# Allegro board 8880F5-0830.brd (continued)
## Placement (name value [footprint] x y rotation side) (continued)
NOREF#2145  -  []  298.49 288.91 90 top
NOREF#2146  -  []  201.49 165.4 90 top
NOREF#2147  -  []  351.04 241.69 0 top
NOREF#2148  -  []  451.68 230.2 0 top
NOREF#2149  -  []  229.51 189.2 0 top
NOREF#2150  -  []  393.74 131.34 90 top
NOREF#2151  -  []  332.51 264.35 90 top
NOREF#2152  -  []  167.7 229.07 90 top
NOREF#2153  -  []  392.24 193.43 0 top
NOREF#2154  -  []  107.18 246.83 90 top
NOREF#2155  -  []  377.32 180.15 0 top
NOREF#2156  -  []  306.71 131.64 0 top
NOREF#2157  -  []  333.4 265.56 0 top
NOREF#2158  -  []  301.56 190.49 0 top
NOREF#2159  -  []  465.31 230.2 0 top
NOREF#2160  -  []  336.77 165.04 90 top
NOREF#2161  -  []  167.7 178.86 90 top
NOREF#2162  -  []  217.83 174.63 90 top
NOREF#2163  -  []  308.14 296.86 0 top
NOREF#2164  -  []  249.6 224.74 90 top
NOREF#2165  -  []  478.57 291.28 90 top
NOREF#2166  -  []  192.47 222.95 90 top
NOREF#2167  -  []  122.44 171.1 0 top
NOREF#2168  -  []  352.55 242.64 0 top
NOREF#2169  -  []  250.17 165.04 90 top
NOREF#2170  -  []  215.96 248.49 0 top
NOREF#2171  -  []  237.83 257.63 0 top
NOREF#2172  -  []  201.23 219.75 90 top
NOREF#2173  -  []  395.2 233.11 0 top
NOREF#2174  -  []  192.47 182.06 90 top
NOREF#2175  -  []  272.25 242.32 90 top
NOREF#2176  -  []  167.7 178.86 90 top
NOREF#2177  -  []  310.43 187.61 90 top
NOREF#2178  -  []  201.49 151.93 90 top
NOREF#2179  -  []  343.98 288.86 0 top
NOREF#2180  -  []  310.43 186.34 0 top
NOREF#2181  -  []  94.68 234.24 0 top
NOREF#2182  -  []  330.73 264.35 90 top
NOREF#2183  -  []  209.23 216.45 90 top
NOREF#2184  -  []  182.57 212.85 0 top
NOREF#2185  -  []  127.81 175.44 90 top
NOREF#2186  -  []  175.8 215.25 90 top
NOREF#2187  -  []  254.29 265.56 90 top
NOREF#2188  -  []  272.25 181.69 0 top
NOREF#2189  -  []  175.7 218.65 90 top
NOREF#2190  -  []  402.14 146.88 0 top
NOREF#2191  -  []  399.39 161.74 0 top
NOREF#2192  -  []  223.56 233.86 90 top
NOREF#2193  -  []  339.65 265.86 90 top
NOREF#2194  -  []  248.96 164.74 0 top
NOREF#2195  -  []  384.36 131.89 0 top
NOREF#2196  -  []  409.49 180.15 0 top
NOREF#2197  -  []  391.8 209.36 0 top
NOREF#2198  -  []  297.83 234.63 90 top
NOREF#2199  -  []  168.13 213.45 90 top
NOREF#2200  -  []  327.57 264.65 90 top
NOREF#2201  -  []  327.25 205.55 0 top
NOREF#2202  -  []  184.47 214 90 top
NOREF#2203  -  []  351.34 245.18 0 top
NOREF#2204  -  []  392.73 154.88 0 top
NOREF#2205  -  []  459.28 227 90 top
NOREF#2206  -  []  449.99 217.9 0 top
NOREF#2207  -  []  320.42 139.64 0 top
NOREF#2208  -  []  322.23 173.13 90 top
NOREF#2209  -  []  122.41 178.64 0 top
NOREF#2210  -  []  167.7 242.78 90 top
NOREF#2211  -  []  371.73 281.11 0 top
NOREF#2212  -  []  265.39 135.19 0 top
NOREF#2213  -  []  234.33 168.13 90 top
NOREF#2214  -  []  184.47 187.92 90 top
NOREF#2215  -  []  270.04 280.1 0 top
NOREF#2216  -  []  223.15 211.32 90 top
NOREF#2217  -  []  201.23 206.29 90 top
NOREF#2218  -  []  313.98 131.19 90 top
NOREF#2219  -  []  413.71 178.82 0 top
NOREF#2220  -  []  397.57 131.89 0 top
NOREF#2221  -  []  262.36 165.04 90 top
NOREF#2222  -  []  182.82 189.04 90 top
NOREF#2223  -  []  184.89 186.02 90 top
NOREF#2224  -  []  222.11 252.14 0 top
NOREF#2225  -  []  251.62 205.56 0 top
NOREF#2226  -  []  309.05 271.67 0 top
NOREF#2227  -  []  175.7 243.88 90 top
NOREF#2228  -  []  390.94 257.16 90 top
NOREF#2229  -  []  259.59 133.29 90 top
NOREF#2230  -  []  467.51 230.2 0 top
NOREF#2231  -  []  192.47 191.22 90 top
NOREF#2232  -  []  397.8 146.43 90 top
NOREF#2233  -  []  155.57 289.11 90 top
NOREF#2234  -  []  251.94 265.86 90 top
NOREF#2235  -  []  422.7 163.64 0 top
NOREF#2236  -  []  272.24 249.18 90 top
NOREF#2237  -  []  248.33 187.93 0 top
NOREF#2238  -  []  101.82 290.38 90 top
NOREF#2239  -  []  328.96 224.72 0 top
NOREF#2240  -  []  300.36 248.49 0 top
NOREF#2241  -  []  342.68 163.52 90 top
NOREF#2242  -  []  472.86 210.36 90 top
NOREF#2243  -  []  230.41 246.34 90 top
NOREF#2244  -  []  313.98 131.09 90 top
NOREF#2245  -  []  194.09 146.68 90 top
NOREF#2246  -  []  295.96 237.06 0 top
NOREF#2247  -  []  325.92 131.64 0 top
NOREF#2248  -  []  462.06 293.82 90 top
NOREF#2249  -  []  330.51 288.86 0 top
NOREF#2250  -  []  124.1 231.22 0 top
NOREF#2251  -  []  394.66 242.38 90 top
NOREF#2252  -  []  424.98 146.33 90 top
NOREF#2253  -  []  263.95 224.74 90 top
NOREF#2254  -  []  167.7 200.54 0 top
NOREF#2255  -  []  115.99 130.36 90 top
NOREF#2256  -  []  343.95 164.74 90 top
NOREF#2257  -  []  388.66 139.89 0 top
NOREF#2258  -  []  112.67 171.02 0 top
NOREF#2259  -  []  250.49 224.74 90 top
NOREF#2260  -  []  201.23 201.89 90 top
NOREF#2261  -  []  250.49 223.52 90 top
NOREF#2262  -  []  482.64 192.46 90 top
NOREF#2263  -  []  369.38 224.6 0 top
NOREF#2264  -  []  117.01 234.24 90 top
NOREF#2265  -  []  354.27 138.37 90 top
NOREF#2266  -  []  485.36 292.02 90 top
NOREF#2267  -  []  389.7 209.36 0 top
NOREF#2268  -  []  330.17 163.82 90 top
NOREF#2269  -  []  342.04 224.72 0 top
NOREF#2270  -  []  471.21 211.76 90 top
NOREF#2271  -  []  175.7 189.02 90 top
NOREF#2272  -  []  346.27 135.17 90 top
NOREF#2273  -  []  209.33 228.97 90 top
NOREF#2274  -  []  375.22 163.39 0 top
NOREF#2275  -  []  120.21 178.64 0 top
NOREF#2276  -  []  210.86 201.29 90 top
NOREF#2277  -  []  383.09 289.12 0 top
NOREF#2278  -  []  385.19 249.11 0 top
NOREF#2279  -  []  310.73 183.41 0 top
NOREF#2280  -  []  378.75 240.56 90 top
NOREF#2281  -  []  194.09 201.29 90 top
NOREF#2282  -  []  272.25 189.18 90 top
NOREF#2283  -  []  167.7 255.15 90 top
NOREF#2284  -  []  127.95 195.15 0 top
NOREF#2285  -  []  366.88 222.7 0 top
NOREF#2286  -  []  394.05 239.21 0 top
NOREF#2287  -  []  415.6 146.88 0 top
NOREF#2288  -  []  250.5 288.86 0 top
NOREF#2289  -  []  406.19 188.15 0 top
NOREF#2290  -  []  229.51 253.69 0 top
NOREF#2291  -  []  453.88 195.91 0 top
NOREF#2292  -  []  404.4 257.42 90 top
NOREF#2293  -  []  386.53 181.42 90 top
NOREF#2294  -  []  182.57 199.39 90 top
NOREF#2295  -  []  342.36 165.04 90 top
NOREF#2296  -  []  201.23 247.18 90 top
NOREF#2297  -  []  167.7 192.32 90 top
NOREF#2298  -  []  301.56 250.49 0 top
NOREF#2299  -  []  405.93 224.56 90 top
NOREF#2300  -  []  66.26 287.84 90 top
NOREF#2301  -  []  182.57 199.39 0 top
NOREF#2302  -  []  230.43 246.34 90 top
NOREF#2303  -  []  329.6 164.74 90 top
NOREF#2304  -  []  237.98 163.82 90 top
NOREF#2305  -  []  199.59 243.9 90 top
NOREF#2306  -  []  450.03 234.74 0 top
NOREF#2307  -  []  309.21 247.61 0 top
NOREF#2308  -  []  413.71 178.82 90 top
NOREF#2309  -  []  400.54 188.15 0 top
NOREF#2310  -  []  367.73 290.39 90 top
NOREF#2311  -  []  271.04 189.82 0 top
NOREF#2312  -  []  404.4 225.16 90 top
NOREF#2313  -  []  237.98 165.04 90 top
NOREF#2314  -  []  263.85 273.37 90 top
NOREF#2315  -  []  401.89 163.64 0 top
NOREF#2316  -  []  184.47 227.72 0 top
NOREF#2317  -  []  528.1 259.9 90 top
NOREF#2318  -  []  230.43 187.61 0 top
NOREF#2319  -  []  184.47 255.15 90 top
NOREF#2320  -  []  239.33 176.03 0 top
NOREF#2321  -  []  119.7 238.84 0 top
NOREF#2322  -  []  118.99 171.65 0 top
NOREF#2323  -  []  332.51 205.55 0 top
NOREF#2324  -  []  398.65 257.37 0 top
NOREF#2325  -  []  252.51 264.35 90 top
NOREF#2326  -  []  346.69 128.87 90 top
NOREF#2327  -  []  218.16 248.49 0 top
NOREF#2328  -  []  258.35 288.91 90 top
NOREF#2329  -  []  184.47 247.18 90 top
NOREF#2330  -  []  314.33 168.13 90 top
NOREF#2331  -  []  309.21 187.61 0 top
NOREF#2332  -  []  210.86 187.32 90 top
NOREF#2333  -  []  392.04 224.85 90 top
NOREF#2334  -  []  318.3 164.74 90 top
NOREF#2335  -  []  199.33 226.57 0 top
NOREF#2336  -  []  518.38 292.92 90 top
NOREF#2337  -  []  248.96 224.74 0 top
NOREF#2338  -  []  418.37 289.17 90 top
NOREF#2339  -  []  528.1 276.41 90 top
NOREF#2340  -  []  237.98 225.04 90 top
NOREF#2341  -  []  263.71 288.86 0 top
NOREF#2342  -  []  313.56 131.64 90 top
NOREF#2343  -  []  309.51 187.93 0 top
NOREF#2344  -  []  252.51 205.55 0 top
NOREF#2345  -  []  327.57 204.65 90 top
NOREF#2346  -  []  272.55 181.37 0 top
NOREF#2347  -  []  192.47 164.3 90 top
NOREF#2348  -  []  277.17 288.86 0 top
NOREF#2349  -  []  471.11 230.2 0 top
NOREF#2350  -  []  392.73 188.15 0 top
NOREF#2351  -  []  106.76 222.88 0 top
NOREF#2352  -  []  405.42 131.94 90 top
NOREF#2353  -  []  175.7 175.56 90 top
NOREF#2354  -  []  201.91 145.63 90 top
NOREF#2355  -  []  392.47 224.3 90 top
NOREF#2356  -  []  265.81 296.86 0 top
NOREF#2357  -  []  396.55 257.37 0 top
NOREF#2358  -  []  230.73 247.93 0 top
NOREF#2359  -  []  182.57 226.57 90 top
NOREF#2360  -  []  94.68 234.24 0 top
NOREF#2361  -  []  296.96 180.71 0 top
NOREF#2362  -  []  249.15 296.86 0 top
NOREF#2363  -  []  175.7 168.6 90 top
NOREF#2364  -  []  418.12 273.37 0 top
NOREF#2365  -  []  118.74 210.19 90 top
NOREF#2366  -  []  332.51 205.56 0 top
NOREF#2367  -  []  385.19 281.11 0 top
NOREF#2368  -  []  262.36 163.82 90 top
NOREF#2369  -  []  127.99 214.79 0 top
NOREF#2370  -  []  408.63 242.38 90 top
NOREF#2371  -  []  329.28 163.82 90 top
NOREF#2372  -  []  315.82 129.74 0 top
NOREF#2373  -  []  309.51 183.41 0 top
NOREF#2374  -  []  221.87 295.91 0 top
NOREF#2375  -  []  124.1 238.84 0 top
NOREF#2376  -  []  388.43 163.64 0 top
NOREF#2377  -  []  184.47 165.4 90 top
NOREF#2378  -  []  290.64 288.86 0 top
NOREF#2379  -  []  408.63 274.64 90 top
NOREF#2380  -  []  392.24 193.43 90 top
NOREF#2381  -  []  465.45 290.38 90 top
NOREF#2382  -  []  351.04 184.23 0 top
NOREF#2383  -  []  254.29 205.55 0 top
NOREF#2384  -  []  481.96 276.41 90 top
NOREF#2385  -  []  411.09 146.88 90 top
NOREF#2386  -  []  285.71 280.1 0 top
NOREF#2387  -  []  327.57 204.65 90 top
NOREF#2388  -  []  463.11 186.77 0 top
NOREF#2389  -  []  199.33 226.57 90 top
NOREF#2390  -  []  234.33 228.13 90 top
NOREF#2391  -  []  192.47 148.38 90 top
NOREF#2392  -  []  392.47 240.66 90 top
NOREF#2393  -  []  416.03 179.42 90 top
NOREF#2394  -  []  283.25 147.43 90 top
NOREF#2395  -  []  379.73 287.22 90 top
NOREF#2396  -  []  229.21 193.37 0 top
NOREF#2397  -  []  184.47 227.72 90 top
NOREF#2398  -  []  262.68 164.74 90 top
NOREF#2399  -  []  237.98 223.82 90 top
NOREF#2400  -  []  201.49 159.65 0 top
NOREF#2401  -  []  272.25 185.5 0 top
NOREF#2402  -  []  412.88 131.89 0 top
NOREF#2403  -  []  415.61 181.32 90 top
NOREF#2404  -  []  373.68 265.11 0 top
NOREF#2405  -  []  264.72 272.65 90 top
NOREF#2406  -  []  401.89 163.64 0 top
NOREF#2407  -  []  251.05 265.86 90 top
NOREF#2408  -  []  269.69 135.19 0 top
NOREF#2409  -  []  342.04 224.74 0 top
NOREF#2410  -  []  209.49 182.06 90 top
NOREF#2411  -  []  351.34 242.64 0 top
NOREF#2412  -  []  230.43 183.09 90 top
NOREF#2413  -  []  201.49 178.86 90 top
NOREF#2414  -  []  253.72 205.86 90 top
NOREF#2415  -  []  461.96 217.98 0 top
NOREF#2416  -  []  199.33 257.62 90 top
NOREF#2417  -  []  383.09 224.85 0 top
NOREF#2418  -  []  385.19 289.12 0 top
NOREF#2419  -  []  387.2 207.46 0 top
NOREF#2420  -  []  118.45 231.77 0 top
NOREF#2421  -  []  412.37 257.37 0 top
NOREF#2422  -  []  199.59 171.96 0 top
NOREF#2423  -  []  271.56 288.91 90 top
NOREF#2424  -  []  184.47 173.11 90 top
NOREF#2425  -  []  381.74 232.85 0 top
NOREF#2426  -  []  342.63 296.86 0 top
NOREF#2427  -  []  460.93 182.17 90 top
NOREF#2428  -  []  453.88 186.77 0 top
NOREF#2429  -  []  250.5 288.86 0 top
NOREF#2430  -  []  331.22 193.63 0 top
NOREF#2431  -  []  263.31 224.74 0 top
NOREF#2432  -  []  267.84 280.1 0 top
NOREF#2433  -  []  450.03 225.6 0 top
NOREF#2434  -  []  316.43 132.91 90 top
NOREF#2435  -  []  346.27 132.97 90 top
NOREF#2436  -  []  410.52 241.11 0 top
NOREF#2437  -  []  400.54 171.64 0 top
NOREF#2438  -  []  184.89 199.99 90 top
NOREF#2439  -  []  423.61 184.62 90 top
NOREF#2440  -  []  251.86 252.43 90 top
NOREF#2441  -  []  456.08 171.53 0 top
NOREF#2442  -  []  274.67 286.96 0 top
NOREF#2443  -  []  119.76 127 90 top
NOREF#2444  -  []  396.03 180.15 0 top
NOREF#2445  -  []  124.64 171.1 0 top
NOREF#2446  -  []  463.11 230.2 0 top
NOREF#2447  -  []  251.94 264.65 90 top
NOREF#2448  -  []  310.43 183.09 0 top
NOREF#2449  -  []  167.7 151.68 90 top
NOREF#2450  -  []  110.47 178.64 0 top
NOREF#2451  -  []  251.94 205.86 90 top
NOREF#2452  -  []  351.04 181.69 0 top
NOREF#2453  -  []  385.19 273.11 0 top
NOREF#2454  -  []  310.43 193.37 90 top
NOREF#2455  -  []  388.43 146.88 0 top
NOREF#2456  -  []  404.4 241.16 90 top
NOREF#2457  -  []  199.33 240.28 90 top
NOREF#2458  -  []  306.83 269.63 90 top
NOREF#2459  -  []  201.49 176.66 90 top
NOREF#2460  -  []  175.7 164.3 90 top
NOREF#2461  -  []  256.77 163.82 90 top
NOREF#2462  -  []  378.75 256.66 90 top
NOREF#2463  -  []  414.82 297.12 0 top
NOREF#2464  -  []  251.62 205.55 0 top
NOREF#2465  -  []  380.59 271.21 0 top
NOREF#2466  -  []  208.98 264.1 90 top
NOREF#2467  -  []  380.53 217.11 0 top
NOREF#2468  -  []  412.24 144.98 90 top
NOREF#2469  -  []  318.3 223.52 90 top
NOREF#2470  -  []  230.73 243.41 0 top
NOREF#2471  -  []  168.13 145.38 90 top
NOREF#2472  -  []  271.04 249.82 0 top
NOREF#2473  -  []  175.7 257.6 90 top
NOREF#2474  -  []  201.66 199.99 90 top
NOREF#2475  -  []  375.22 163.39 0 top
NOREF#2476  -  []  238.45 197.01 0 top
NOREF#2477  -  []  239.33 176.03 90 top
NOREF#2478  -  []  218.13 214.06 0 top
NOREF#2479  -  []  352.25 189.82 0 top
NOREF#2480  -  []  273.09 288.31 90 top
NOREF#2481  -  []  118.74 215.34 0 top
NOREF#2482  -  []  396.28 180.2 90 top
NOREF#2483  -  []  272.55 189.5 0 top
NOREF#2484  -  []  330.73 265.56 0 top
NOREF#2485  -  []  375.22 163.39 0 top
NOREF#2486  -  []  297.41 213.24 90 top
NOREF#2487  -  []  199.33 185.42 0 top
NOREF#2488  -  []  303.84 288.86 0 top
NOREF#2489  -  []  201.23 217.55 90 top
NOREF#2490  -  []  405.93 256.82 90 top
NOREF#2491  -  []  201.49 173.11 0 top
NOREF#2492  -  []  118.45 239.39 0 top
NOREF#2493  -  []  388.43 163.64 0 top
NOREF#2494  -  []  108.27 178.64 0 top
NOREF#2495  -  []  392.04 257.11 90 top
NOREF#2496  -  []  352.24 241.05 90 top
NOREF#2497  -  []  229.51 243.41 0 top
NOREF#2498  -  []  237.66 224.72 0 top
NOREF#2499  -  []  247.78 132.14 90 top
NOREF#2500  -  []  326 288.86 90 top
NOREF#2501  -  []  209.49 164.3 90 top
NOREF#2502  -  []  221.56 239.06 0 top
NOREF#2503  -  []  310.43 243.09 0 top
NOREF#2504  -  []  334.61 264.65 90 top
NOREF#2505  -  []  392.73 171.64 0 top
NOREF#2506  -  []  337.09 164.74 90 top
NOREF#2507  -  []  555.66 300.54 90 top
NOREF#2508  -  []  317.57 209.63 90 top
NOREF#2509  -  []  184.47 206.29 90 top
NOREF#2510  -  []  334.81 296.86 0 top
NOREF#2511  -  []  405.93 224.66 90 top
NOREF#2512  -  []  381.2 274.38 90 top
NOREF#2513  -  []  257.09 163.52 90 top
NOREF#2514  -  []  340.61 286.96 90 top
NOREF#2515  -  []  272.24 244.86 90 top
NOREF#2516  -  []  408.92 265.37 0 top
NOREF#2517  -  []  106.76 215.26 0 top
NOREF#2518  -  []  301.56 239.06 0 top
NOREF#2519  -  []  330.73 205.56 0 top
NOREF#2520  -  []  250.18 182.88 0 top
NOREF#2521  -  []  271.04 184.23 0 top
NOREF#2522  -  []  271.34 181.37 0 top
NOREF#2523  -  []  116.01 214.71 0 top
NOREF#2524  -  []  344.37 128.27 0 top
NOREF#2525  -  []  473.79 239.64 0 top
NOREF#2526  -  []  271.04 245.5 0 top
NOREF#2527  -  []  230.43 247.61 0 top
NOREF#2528  -  []  392.47 256.66 90 top
NOREF#2529  -  []  396.55 225.11 0 top
NOREF#2530  -  []  168.69 273.5 90 top
NOREF#2531  -  []  167.7 215.35 90 top
NOREF#2532  -  []  415.1 163.64 0 top
NOREF#2533  -  []  127.7 231.22 0 top
NOREF#2534  -  []  201.23 233.47 90 top
NOREF#2535  -  []  105.58 234.24 90 top
NOREF#2536  -  []  184.47 204.09 90 top
NOREF#2537  -  []  165.8 226.57 0 top
NOREF#2538  -  []  310.41 253.37 90 top
NOREF#2539  -  []  337.9 186.35 90 top
NOREF#2540  -  []  309.51 193.69 0 top
NOREF#2541  -  []  219.81 273.69 90 top
NOREF#2542  -  []  237.57 209.63 90 top
NOREF#2543  -  []  385.32 161.49 90 top
NOREF#2544  -  []  175.7 259.8 90 top
NOREF#2545  -  []  165.8 212.85 0 top
NOREF#2546  -  []  324.65 288.86 0 top
NOREF#2547  -  []  167.7 227.72 90 top
NOREF#2548  -  []  94.93 190.55 0 top
NOREF#2549  -  []  331.05 264.65 90 top
NOREF#2550  -  []  419.73 131.89 90 top
NOREF#2551  -  []  386.46 131.89 0 top
NOREF#2552  -  []  343.83 231.63 90 top
NOREF#2553  -  []  259.97 204.35 90 top
NOREF#2554  -  []  354.37 130.67 90 top
NOREF#2555  -  []  75.98 273.87 90 top
NOREF#2556  -  []  417.7 146.88 0 top
NOREF#2557  -  []  461.96 210.36 0 top
NOREF#2558  -  []  250.17 163.82 90 top
NOREF#2559  -  []  310.41 183.09 90 top
NOREF#2560  -  []  118.33 286.94 90 top
NOREF#2561  -  []  251.62 205.56 90 top
NOREF#2562  -  []  471.21 175.95 90 top
NOREF#2563  -  []  398.65 209.36 90 top
NOREF#2564  -  []  175.7 182.06 90 top
NOREF#2565  -  []  175.7 150.58 90 top
NOREF#2566  -  []  254.29 265.56 0 top
NOREF#2567  -  []  262.68 223.52 90 top
NOREF#2568  -  []  405.51 209.61 0 top
NOREF#2569  -  []  404.15 241.11 0 top
NOREF#2570  -  []  352.25 243.59 90 top
NOREF#2571  -  []  167.7 241.43 0 top
NOREF#2572  -  []  166.06 243.9 90 top
R1  NC/1M-1-S4  [R0402]  221.23 227.84 180 bottom
R2  NC/1M-1-S4  [R0402]  218.95 227.84 0 bottom
R3  NC/100K-1-S4  [R0402]  184.15 131.06 180 bottom
R4  NC/100K-1-S4  [R0402]  181.61 131.06 180 bottom
R5  0-5-S4  [R0402]  222.38 272.16 270 bottom
R6  1M-1-S4  [R0402]  222.38 274.32 270 bottom
R7  49.9-1-S4  [R0402]  349.4 299.66 180 bottom
R8  49.9-1-S4  [R0402]  351.55 299.66 180 bottom
R9  49.9-1-S4  [R0402]  349.4 286.07 180 bottom
R10  49.9-1-S4  [R0402]  351.55 286.07 180 bottom
R11  49.9-1-S4  [R0402]  335.94 299.66 180 bottom
R12  49.9-1-S4  [R0402]  338.09 299.66 180 bottom
R13  49.9-1-S4  [R0402]  335.94 286.07 180 bottom
R14  49.9-1-S4  [R0402]  338.09 286.07 180 bottom
R15  49.9-1-S4  [R0402]  322.48 299.66 180 bottom
R16  49.9-1-S4  [R0402]  324.62 299.66 180 bottom
R17  49.9-1-S4  [R0402]  322.48 286.07 180 bottom
R18  49.9-1-S4  [R0402]  324.62 286.07 180 bottom
R19  49.9-1-S4  [R0402]  287.88 269.3 0 bottom
R20  49.9-1-S4  [R0402]  285.74 269.3 0 bottom
R21  49.9-1-S4  [R0402]  287.88 282.89 0 bottom
R22  49.9-1-S4  [R0402]  285.74 282.89 0 bottom
R23  49.9-1-S4  [R0402]  309.27 299.66 180 bottom
R24  49.9-1-S4  [R0402]  311.42 299.66 180 bottom
R25  49.9-1-S4  [R0402]  309.27 286.07 180 bottom
R26  49.9-1-S4  [R0402]  311.42 286.07 180 bottom
R27  49.9-1-S4  [R0402]  296.06 299.66 180 bottom
R28  49.9-1-S4  [R0402]  298.21 299.66 180 bottom
R29  49.9-1-S4  [R0402]  296.06 286.07 180 bottom
R30  49.9-1-S4  [R0402]  298.21 286.07 180 bottom
R31  49.9-1-S4  [R0402]  282.6 299.66 180 bottom
R32  49.9-1-S4  [R0402]  284.75 299.66 180 bottom
R33  49.9-1-S4  [R0402]  282.6 286.07 180 bottom
R34  49.9-1-S4  [R0402]  284.75 286.07 180 bottom
R37  49.9-1-S4  [R0402]  269.14 286.07 180 bottom
R38  49.9-1-S4  [R0402]  271.28 286.07 180 bottom
R39  49.9-1-S4  [R0402]  255.93 299.66 180 bottom
R40  49.9-1-S4  [R0402]  258.08 299.66 180 bottom
R41  49.9-1-S4  [R0402]  255.93 286.07 180 bottom
R42  49.9-1-S4  [R0402]  258.08 286.07 180 bottom
R43  49.9-1-S4  [R0402]  164.91 258.67 90 bottom
R44  49.9-1-S4  [R0402]  164.91 256.53 90 bottom
R45  49.9-1-S4  [R0402]  198.44 231.24 90 bottom
R46  49.9-1-S4  [R0402]  198.44 229.1 90 bottom
R47  49.9-1-S4  [R0402]  178.5 217.52 90 bottom
R48  49.9-1-S4  [R0402]  178.5 215.38 90 bottom
R49  49.9-1-S4  [R0402]  164.91 217.52 90 bottom
R50  49.9-1-S4  [R0402]  164.91 215.38 90 bottom
R51  49.9-1-S4  [R0402]  195.26 231.24 90 bottom
R52  49.9-1-S4  [R0402]  195.26 229.1 90 bottom
R53  49.9-1-S4  [R0402]  181.67 231.24 90 bottom
R54  49.9-1-S4  [R0402]  181.67 229.1 90 bottom
R55  49.9-1-S4  [R0402]  212.03 244.96 90 bottom
R56  49.9-1-S4  [R0402]  212.03 242.81 90 bottom
R57  49.9-1-S4  [R0402]  198.44 244.96 90 bottom
R58  49.9-1-S4  [R0402]  198.44 242.81 90 bottom
R59  49.9-1-S4  [R0402]  178.5 231.24 90 bottom
R60  49.9-1-S4  [R0402]  178.5 229.1 90 bottom
R61  49.9-1-S4  [R0402]  164.91 231.24 90 bottom
R62  49.9-1-S4  [R0402]  164.91 229.1 90 bottom
R63  49.9-1-S4  [R0402]  178.5 244.96 90 bottom
R64  49.9-1-S4  [R0402]  178.5 242.81 90 bottom
R65  49.9-1-S4  [R0402]  181.67 244.96 90 bottom
R66  49.9-1-S4  [R0402]  181.67 242.81 90 bottom
R67  49.9-1-S4  [R0402]  239.37 285.81 0 bottom
R68  49.9-1-S4  [R0402]  237.22 285.81 0 bottom
R69  49.9-1-S4  [R0402]  239.37 299.4 0 bottom
R70  49.9-1-S4  [R0402]  237.22 299.4 0 bottom
R71  49.9-1-S4  [R0402]  195.26 258.67 90 bottom
R72  49.9-1-S4  [R0402]  195.26 256.53 90 bottom
R73  49.9-1-S4  [R0402]  181.67 258.67 90 bottom
R74  49.9-1-S4  [R0402]  181.67 256.53 90 bottom
R75  49.9-1-S4  [R0402]  211.77 258.67 90 bottom
R76  49.9-1-S4  [R0402]  211.77 256.53 90 bottom
R77  49.9-1-S4  [R0402]  198.18 258.67 90 bottom
R78  49.9-1-S4  [R0402]  198.18 256.53 90 bottom
R79  49.9-1-S4  [R0402]  178.5 258.67 90 bottom
R80  49.9-1-S4  [R0402]  178.5 256.53 90 bottom
R82  4.7K-1-S4-WA  [R0402]  122.62 241.1 180 bottom
R83  4.7K-1-S4-WA  [R0402]  96.77 233.43 180 bottom
R84  4.7K-1-S4-WA  [R0402]  96.77 241.05 180 bottom
R85  100K-1-S4  [R0402]  113.79 230.12 180 bottom
R86  4.7K-1-S4-WA  [R0402]  93.33 207.46 180 bottom
R87  4.7K-1-S4-WA  [R0402]  104.14 203.31 180 bottom
R88  4.7K-1-S4-WA  [R0402]  101.6 203.31 180 bottom
R89  4.7K-1-S4-WA  [R0402]  89.03 207.41 0 bottom
R90  4.7K-1-S4-WA  [R0402]  101.6 215.5 180 bottom
R91  4.7K-1-S4-WA  [R0402]  99.06 215.5 180 bottom
R92  4.7K-1-S4-WA  [R0402]  96.52 215.5 180 bottom
R93  4.7K-1-S4-WA  [R0402]  93.33 221.18 180 bottom
R94  4.7K-1-S4-WA  [R0402]  104.25 216.86 0 bottom
R95  4.7K-1-S4-WA  [R0402]  101.7 216.91 180 bottom
R96  4.7K-1-S4-WA  [R0402]  89.27 221.18 0 bottom
R97  4.7K-1-S4-WA  [R0402]  101.7 229.1 180 bottom
R98  4.7K-1-S4-WA  [R0402]  99.16 229.1 180 bottom
R99  4.7K-1-S4-WA  [R0402]  96.62 229.1 180 bottom
R100  49.9-1-S4  [R0402]  164.91 244.96 90 bottom
R101  49.9-1-S4  [R0402]  164.91 242.81 90 bottom
R102  49.9-1-S4  [R0402]  212.03 231.24 90 bottom
R103  49.9-1-S4  [R0402]  212.03 229.1 90 bottom
R104  49.9-1-S4  [R0402]  195.26 244.96 90 bottom
R105  49.9-1-S4  [R0402]  195.26 242.81 90 bottom
R117  1K-1-S4  [R0402]  127.2 241.1 180 bottom
R118  NC/0-5-S4  [R0402]  230.41 245.39 180 bottom
R119  4.7K-1-S4-WA  [R0402]  127.25 233.43 0 bottom
R120  4.7K-1-S4-WA  [R0402]  127.25 225.81 0 bottom
R125  0-5-S4  [R0402]  123.19 224.54 180 bottom
R126  0-5-S4  [R0402]  127.25 224.54 180 bottom
R127  0-5-S4  [R0402]  122.94 216.92 180 bottom
R128  0-5-S4  [R0402]  127.51 216.92 180 bottom
R129  0-5-S4  [R0402]  221.23 229.11 180 bottom
R130  0-5-S4  [R0402]  218.95 229.11 0 bottom
R131  50-0.1-S4-HF-VI  [R0402]  223.77 243.33 90 bottom
R132  50-0.1-S4-HF-VI  [R0402]  216.15 243.33 90 bottom
R133  0-5-S4  [R0402]  222.38 276.48 90 bottom
RB1  10K-1-S6  [R0603]  212.47 13.59 0 bottom
RB2  10K-1-S6  [R0603]  212.47 12.06 0 bottom
S1_I2C  HDR-4X1-MR-A  [JP_4P_100_R90_V1]  62.99 209.04 270 top
S1_RST_N  HDR-2X1-M  [JP_2P_100]  115.82 232.41 270 bottom
S2_I2C  HDR-4X1-MR-A  [JP_4P_100_R90_V1]  497.33 203.45 270 top
S2_RST_N  HDR-2X1-M  [JP_2P_100]  463.04 233.43 90 bottom
S3_I2C  HDR-4X1-MR-A  [JP_4P_100_R90_V1]  75.69 209.04 270 top
S3_RST_N  HDR-2X1-M  [JP_2P_100]  116.08 188.72 270 bottom
S4_I2C  HDR-4X1-MR-A  [JP_4P_100_R90_V1]  511.3 203.45 270 top
S4_RST_N  HDR-2X1-M  [JP_2P_100]  463.04 189.99 90 bottom
SB1  SHORT  [DEFAULT_SHORT_SMALL]  402.59 11.04 90 top
SB2  SHORT  [DEFAULT_SHORT_SMALL]  328.93 417.83 270 top
SB3  SHORT  [DEFAULT_SHORT_SMALL]  255.27 11.71 90 top
SB8  SHORT  [DEFAULT_SHORT_SMALL]  179.07 418.32 270 top
SCREW1  V93KMFHOLE  [PG_VG93K_F_FULLOUTLINE]  290.83 214.63 0 top
SH1  SHORT  [DEFAULT_SHORT_SMALL]  185.19 290.72 0 top
SH2  SHORT  [DEFAULT_SHORT_SMALL]  187.14 290.72 0 top
SH3  SHORT  [DEFAULT_SHORT_SMALL]  175.35 290.72 0 top
SH4  SHORT  [DEFAULT_SHORT_SMALL]  173.4 290.85 180 top
SH5  SHORT  [DEFAULT_SHORT_SMALL]  118.2 289.45 0 top
SH6  SHORT  [DEFAULT_SHORT_SMALL]  116.25 289.58 180 top
SH7  SHORT  [DEFAULT_SHORT_SMALL]  168.68 290.72 0 top
SH8  SHORT  [DEFAULT_SHORT_SMALL]  156.89 290.85 180 top
SH9  SHORT  [DEFAULT_SHORT_SMALL]  170.63 290.72 0 top
SH10  SHORT  [DEFAULT_SHORT_SMALL]  158.84 290.72 0 top
SH11  SHORT  [DEFAULT_SHORT_SMALL]  173.4 274.34 180 top
SH12  SHORT  [DEFAULT_SHORT_SMALL]  185.19 274.21 0 top
SH13  SHORT  [DEFAULT_SHORT_SMALL]  203.14 290.72 0 top
SH14  SHORT  [DEFAULT_SHORT_SMALL]  201.19 290.72 0 top
SH15  SHORT  [DEFAULT_SHORT_SMALL]  189.4 290.85 180 top
SH16  SHORT  [DEFAULT_SHORT_SMALL]  191.35 290.72 0 top
SH17  SHORT  [DEFAULT_SHORT_SMALL]  156.89 274.34 180 top
SH18  SHORT  [DEFAULT_SHORT_SMALL]  168.68 274.21 0 top
SH19  SHORT  [DEFAULT_SHORT_SMALL]  99.42 246.45 0 top
SH20  SHORT  [DEFAULT_SHORT_SMALL]  101.62 246.45 0 top
SH21  SHORT  [DEFAULT_SHORT_SMALL]  94.56 246.5 0 top
SH22  SHORT  [DEFAULT_SHORT_SMALL]  96.76 246.5 0 top
SH23  SHORT  [DEFAULT_SHORT_SMALL]  201.19 274.21 0 top
SH24  SHORT  [DEFAULT_SHORT_SMALL]  203.37 274.08 180 top
SH25  SHORT  [DEFAULT_SHORT_SMALL]  175.35 274.21 0 top
SH26  SHORT  [DEFAULT_SHORT_SMALL]  187.14 274.21 0 top
SH27  SHORT  [DEFAULT_SHORT_SMALL]  158.84 274.21 0 top
SH28  SHORT  [DEFAULT_SHORT_SMALL]  170.63 274.21 0 top
SITE1  CU/HX8880-F05-LQFP176-20X20  [SK_LQFP176P_0P4MM_JG_HX8880]  250.83 244.63 90 top
SITE2  CU/HX8880-F05-LQFP176-20X20  [SK_LQFP176P_0P4MM_JG_HX8880]  330.83 244.63 90 top
SITE3  CU/HX8880-F05-LQFP176-20X20  [SK_LQFP176P_0P4MM_JG_HX8880]  250.83 184.63 90 top
SITE4  CU/HX8880-F05-LQFP176-20X20  [SK_LQFP176P_0P4MM_JG_HX8880]  330.83 184.63 90 top
SKB  Socket_Base_M5_140x140  [SOCKET_BASE_140X140_565100]  290.83 214.63 0 top
TP_AUXVCC  TP01  [TP_040_T]  101.29 247.61 180 top
TP_AVDD11_RX  TP01  [TP_040_T]  158.96 292.1 180 top
TP_AVDD11_XTAL  TP01  [TP_040_T]  201.21 275.59 0 top
TP_AVDD18_RX  TP01  [TP_040_T]  168.7 292.1 0 top
TP_PLL_M_VDD33  TP01  [TP_040_T]  201.21 292.1 0 top
TP_PLL_TX_VDD33  TP01  [TP_040_T]  191.48 292.1 180 top
TP_VCC3V3  TP01  [TP_040_T]  96.42 247.66 180 top
TP_VDD_IO_33  TP01  [TP_040_T]  175.47 292.1 180 top
TP_VDD_TXREG_33_B  TP01  [TP_040_T]  168.7 275.59 0 top
TP_VDD_TXREG_33_T  TP01  [TP_040_T]  158.96 275.59 180 top
TP_VDDA_33_LV  TP01  [TP_040_T]  185.21 292.1 0 top
TP_VDDC_11  TP01  [TP_040_T]  118.32 290.83 180 top
TP_VDDTXPST_11_B  TP01  [TP_040_T]  185.21 275.59 0 top
TP_VDDTXPST_11_T  TP01  [TP_040_T]  175.47 275.59 180 top
TP_XTAL_IN  TP01  [TP_040_T]  226.85 271.67 0 top
TP_XTAL_OUT  TP01  [TP_040_T]  226.85 276.97 0 top
TPL1  TPL01  [TPL_040_014_TB]  73.41 239.01 0 top
TPL2  TPL01  [TPL_040_014_TB]  78.49 244.09 0 top
TPL3  TPL01  [TPL_040_014_TB]  68.33 228.85 0 top
TPL4  TPL01  [TPL_040_014_TB]  68.33 239.01 0 top
TPL5  TPL01  [TPL_040_014_TB]  73.41 244.09 0 top
TPL6  TPL01  [TPL_040_014_TB]  68.33 233.93 0 top
TPL7  TPL01  [TPL_040_014_TB]  78.49 233.93 0 top
TPL8  TPL01  [TPL_040_014_TB]  73.41 233.93 0 top
TPL9  TPL01  [TPL_040_014_TB]  68.33 244.09 0 top
TPL10  TPL01  [TPL_040_014_TB]  78.49 239.01 0 top
TPL11  TPL01  [TPL_040_014_TB]  73.41 218.69 0 top
TPL12  TPL01  [TPL_040_014_TB]  78.49 218.69 0 top
TPL13  TPL01  [TPL_040_014_TB]  83.57 223.77 0 top
TPL14  TPL01  [TPL_040_014_TB]  83.57 218.69 0 top
TPL15  TPL01  [TPL_040_014_TB]  73.41 228.85 0 top
TPL16  TPL01  [TPL_040_014_TB]  68.33 223.77 0 top
TPL17  TPL01  [TPL_040_014_TB]  68.33 218.69 0 top
TPL18  TPL01  [TPL_040_014_TB]  78.49 223.77 0 top
TPL19  TPL01  [TPL_040_014_TB]  73.41 223.77 0 top
TPL20  TPL01  [TPL_040_014_TB]  78.49 228.85 0 top
TPL21  TPL01  [TPL_040_014_TB]  452.63 249.17 0 top
TPL22  TPL01  [TPL_040_014_TB]  452.63 259.33 0 top
TPL23  TPL01  [TPL_040_014_TB]  452.63 264.41 0 top
TPL24  TPL01  [TPL_040_014_TB]  452.63 254.25 0 top
TPL25  TPL01  [TPL_040_014_TB]  452.63 244.09 0 top
TPL26  TPL01  [TPL_040_014_TB]  457.71 244.09 0 top
TPL27  TPL01  [TPL_040_014_TB]  452.63 269.49 0 top
TPL28  TPL01  [TPL_040_014_TB]  457.71 249.17 0 top
TPL29  TPL01  [TPL_040_014_TB]  457.71 269.49 0 top
TPL30  TPL01  [TPL_040_014_TB]  457.71 264.41 0 top
TPL31  TPL01  [TPL_040_014_TB]  457.71 259.33 0 top
TPL32  TPL01  [TPL_040_014_TB]  457.71 254.25 0 top
TPL33  TPL01  [TPL_040_014_TB]  462.79 244.09 0 top
TPL34  TPL01  [TPL_040_014_TB]  467.87 249.17 0 top
TPL35  TPL01  [TPL_040_014_TB]  467.87 244.09 0 top
TPL36  TPL01  [TPL_040_014_TB]  462.79 249.17 0 top
TPL37  TPL01  [TPL_040_014_TB]  462.79 269.49 0 top
TPL38  TPL01  [TPL_040_014_TB]  462.79 259.33 0 top
TPL39  TPL01  [TPL_040_014_TB]  462.79 254.25 0 top
TPL40  TPL01  [TPL_040_014_TB]  462.79 264.41 0 top
U1  SOLDER-DIP8-SOCKET  [DIP8_300X100_RLPIN]  104.66 205.54 90 bottom
U2  SOLDER-DIP8-SOCKET  [DIP8_300X100_RLPIN]  104.76 219.15 90 bottom
UB1  AT24C04C-SSHM-SO8  [SO8_215X127MM]  218.44 13.97 180 bottom
UF1  MX25L4006EM2I-12G-SOP8  [SOCKET_CODE]  104.66 205.54 270 top
UF2  MX25L4006EM2I-12G-SOP8  [SOCKET_CODE]  104.75 219.2 270 top
UNK2C3  0.1U-16-X-S4-MU  [C0402]  289.81 132.08 180 bottom
UNK2C4  0.1U-16-X-S4-MU  [C0402]  287.27 132.08 180 bottom
UNK2C5  22P-50-N-S4-AVX  [C0402]  301.21 277.48 90 bottom
UNK2C6  22P-50-N-S4-AVX  [C0402]  301.21 271.16 270 bottom
UNK2C7  0.1U-16-X-S4-MU  [C0402]  468.12 235.71 180 bottom
UNK2C8  0.1U-16-X-S4-MU  [C0402]  475.39 204.98 0 bottom
UNK2C9  0.1U-16-X-S4-MU  [C0402]  475.49 218.59 0 bottom
UNK2CA1  NC/10U-10-X6S-S6-MU  [C0603]  462.91 293.37 0 bottom
UNK2CA2  NC/47U-10-X5R-S8-TDK  [C0805]  463.02 295.27 0 bottom
UNK2CA3  NC/10U-10-X6S-S6-MU  [C0603]  451.49 293.37 180 bottom
UNK2CA4  NC/47U-10-X5R-S8-TDK  [C0805]  451.38 295.27 180 bottom
UNK2CA5  NC/10U-10-X6S-S6-MU  [C0603]  484.5 293.37 180 bottom
UNK2CA6  NC/47U-10-X5R-S8-TDK  [C0805]  484.4 295.27 180 bottom
UNK2CA7  NC/10U-10-X6S-S6-MU  [C0603]  462.91 276.86 0 bottom
UNK2CA8  NC/47U-10-X5R-S8-TDK  [C0805]  463.02 278.76 0 bottom
UNK2CA9  NC/10U-10-X6S-S6-MU  [C0603]  451.49 276.86 180 bottom
UNK2CA10  NC/47U-10-X5R-S8-TDK  [C0805]  451.38 278.76 180 bottom
UNK2CA11  NC/10U-10-X6S-S6-MU  [C0603]  495.93 276.86 0 bottom
UNK2CA12  NC/47U-10-X5R-S8-TDK  [C0805]  496.04 278.76 0 bottom
UNK2CA13  NC/47U-10-X5R-S8-TDK  [C0805]  479.53 295.27 0 bottom
UNK2CA14  NC/10U-10-X6S-S6-MU  [C0603]  479.42 293.37 0 bottom
UNK2CA15  NC/47U-10-X5R-S8-TDK  [C0805]  467.89 295.27 180 bottom
UNK2CA16  NC/10U-10-X6S-S6-MU  [C0603]  468 293.37 180 bottom
UNK2CA17  NC/47U-10-X5R-S8-TDK  [C0805]  479.53 278.76 0 bottom
UNK2CA18  NC/10U-10-X6S-S6-MU  [C0603]  479.42 276.86 0 bottom
UNK2CA19  NC/47U-10-X5R-S8-TDK  [C0805]  91.09 249.81 180 bottom
UNK2CA20  NC/10U-10-X6S-S6-MU  [C0603]  91.19 247.9 180 bottom
UNK2CA21  10U-10-X6S-S6-MU  [C0603]  462.91 290.83 0 bottom
UNK2CA22  10U-10-X6S-S6-MU  [C0603]  451.49 290.83 180 bottom
UNK2CA23  10U-10-X6S-S6-MU  [C0603]  484.5 290.83 180 bottom
UNK2CA24  10U-10-X6S-S6-MU  [C0603]  462.91 274.32 0 bottom
UNK2CA25  10U-10-X6S-S6-MU  [C0603]  451.49 274.32 180 bottom
UNK2CA26  10U-10-X6S-S6-MU  [C0603]  495.93 274.32 0 bottom
UNK2CA27  10U-10-X6S-S6-MU  [C0603]  479.42 290.83 0 bottom
UNK2CA28  10U-10-X6S-S6-MU  [C0603]  468 290.83 180 bottom
UNK2CA29  10U-10-X6S-S6-MU  [C0603]  479.42 274.32 0 bottom
UNK2CA30  NC/47U-10-X5R-S8-TDK  [C0805]  86.22 249.86 180 bottom
UNK2CA31  10U-10-X6S-S6-MU  [C0603]  86.32 247.96 180 bottom
UNK2CA32  NC/10U-10-X6S-S6-MU  [C0603]  512.44 293.37 0 bottom
UNK2CA33  NC/47U-10-X5R-S8-TDK  [C0805]  512.55 295.27 0 bottom
UNK2CA34  10U-10-X6S-S6-MU  [C0603]  512.44 290.83 0 bottom
UNK2CA35  NC/10U-10-X6S-S6-MU  [C0603]  484.5 276.86 180 bottom
UNK2CA36  NC/47U-10-X5R-S8-TDK  [C0805]  484.4 278.76 180 bottom
UNK2CA37  10U-10-X6S-S6-MU  [C0603]  484.5 274.32 180 bottom
UNK2CA38  NC/10U-10-X6S-S6-MU  [C0603]  468 276.86 180 bottom
UNK2CA39  NC/47U-10-X5R-S8-TDK  [C0805]  467.89 278.76 180 bottom
UNK2CA40  10U-10-X6S-S6-MU  [C0603]  468 274.32 180 bottom
UNK2CC1  0.47U-10-X6S-S2-TY  [C0201]  317.98 224.12 90 bottom
UNK2CC2  4.7U-10-X6T-S4-MU  [C0402]  316.32 222.4 270 bottom
UNK2CC4  0.47U-10-X6S-S2-TY  [C0201]  309.81 247.93 0 bottom
UNK2CC6  0.47U-10-X6S-S2-TY  [C0201]  330.17 224.12 90 bottom
UNK2CC7  0.47U-10-X6S-S2-TY  [C0201]  309.81 246.66 0 bottom
UNK2CC8  0.47U-10-X6S-S2-TY  [C0201]  343.63 224.12 90 bottom
UNK2CC9  0.47U-10-X6S-S2-TY  [C0201]  334.61 266.16 270 bottom
UNK2CC11  0.47U-10-X6S-S2-TY  [C0201]  331.06 224.12 90 bottom
UNK2CC13  0.47U-10-X6S-S2-TY  [C0201]  336.77 224.12 90 bottom
UNK2CC15  4.7U-2.5-X6S-S2-MU  [C0201]  339.65 264.95 90 bottom
UNK2CC16  NC/4.7U-2.5-X6S-S2-MU  [C0201]  351.64 249.5 0 bottom
UNK2CC17  4.7U-2.5-X6S-S2-MU  [C0201]  309.81 253.69 0 bottom
UNK2CC19  0.47U-10-X6S-S2-TY  [C0201]  332.83 266.16 270 bottom
UNK2CC20  4.7U-10-X6T-S4-MU  [C0402]  334.11 267.66 0 bottom
UNK2CC22  0.47U-10-X6S-S2-TY  [C0201]  331.05 266.16 270 bottom
UNK2CC23  4.7U-10-X6T-S4-MU  [C0402]  330.34 253.09 270 bottom
UNK2CC25  0.47U-10-X6S-S2-TY  [C0201]  352.85 245.18 180 bottom
UNK2CC26  0.47U-10-X6S-S2-TY  [C0201]  333.72 266.16 270 bottom
UNK2CC27  0.47U-10-X6S-S2-TY  [C0201]  352.85 249.5 180 bottom
UNK2CC28  0.47U-10-X6S-S2-TY  [C0201]  339.65 266.16 270 bottom
UNK2CC29  0.47U-10-X6S-S2-TY  [C0201]  311.03 253.69 180 bottom
UNK2CC30  0.47U-10-X6S-S2-TY  [C0201]  309.81 243.41 0 bottom
UNK2CC31  0.47U-10-X6S-S2-TY  [C0201]  329.28 224.12 90 bottom
UNK2CC32  0.47U-10-X6S-S2-TY  [C0201]  342.36 224.12 90 bottom
UNK2CC33  0.47U-10-X6S-S2-TY  [C0201]  352.85 243.91 180 bottom
UNK2CC34  0.47U-10-X6S-S2-TY  [C0201]  331.94 266.16 270 bottom
UNK2CC35  0.47U-10-X6S-S2-TY  [C0201]  352.85 241.37 180 bottom
UNK2CC36  0.47U-10-X6S-S2-TY  [C0201]  352.85 242.64 180 bottom
UNK2CC37  0.47U-10-X6S-S2-TY  [C0201]  327.57 264.95 90 bottom
UNK2CC38  NC/4.7U-2.5-X6S-S2-MU  [C0201]  327.57 266.16 270 bottom
UNK2CC39  0.47U-10-X6S-S2-TY  [C0201]  311.03 249.2 180 bottom
UNK2CC40  4.7U-2.5-X6S-S2-MU  [C0201]  338.5 246.67 180 bottom
UNK2CC41  4.7U-2.5-X6S-S2-MU  [C0201]  309.81 249.2 0 bottom
UNK2CC42  4.7U-2.5-X6S-S2-MU  [C0201]  331.54 253.03 90 bottom
UNK2CD1  0.1U-10-X7R-S2-MU  [C0201]  317.98 225.34 270 top
UNK2CD3  0.1U-10-X7R-S2-MU  [C0201]  351.64 241.37 0 top
UNK2CD4  0.1U-10-X7R-S2-MU  [C0201]  334.61 264.95 90 top
UNK2CD5  0.1U-10-X7R-S2-MU  [C0201]  343.63 225.34 270 top
UNK2CD6  0.1U-10-X7R-S2-MU  [C0201]  311.03 246.66 180 top
UNK2CD7  0.1U-10-X7R-S2-MU  [C0201]  351.64 242.64 0 top
UNK2CD8  0.1U-10-X7R-S2-MU  [C0201]  331.06 225.34 270 top
UNK2CD9  0.1U-10-X7R-S2-MU  [C0201]  336.77 225.34 270 top
UNK2CD10  0.1U-10-X7R-S2-MU  [C0201]  351.64 249.5 0 top
UNK2CD11  0.1U-10-X7R-S2-MU  [C0201]  339.65 264.95 90 top
UNK2CD12  0.1U-10-X7R-S2-MU  [C0201]  311.03 253.69 180 top
UNK2CD13  0.1U-10-X7R-S2-MU  [C0201]  332.83 264.95 90 top
UNK2CD14  0.1U-10-X7R-S2-MU  [C0201]  331.05 264.95 90 top
UNK2CD15  0.1U-10-X7R-S2-MU  [C0201]  351.64 245.18 0 top
UNK2CD16  0.1U-10-X7R-S2-MU  [C0201]  333.72 264.95 90 top
UNK2CD17  0.1U-10-X7R-S2-MU  [C0201]  311.03 247.93 180 top
UNK2CD18  0.1U-10-X7R-S2-MU  [C0201]  331.94 264.95 90 top
UNK2CD19  0.1U-10-X7R-S2-MU  [C0201]  311.03 243.41 180 top
UNK2CD20  0.1U-10-X7R-S2-MU  [C0201]  351.64 243.91 0 top
UNK2CD21  0.1U-10-X7R-S2-MU  [C0201]  342.36 225.34 270 top
UNK2CD22  0.1U-10-X7R-S2-MU  [C0201]  329.28 225.34 270 top
UNK2CD23  0.1U-10-X7R-S2-MU  [C0201]  330.17 225.34 270 top
UNK2CD24  0.1U-10-X7R-S2-MU  [C0201]  327.57 264.95 90 top
UNK2CD25  0.1U-10-X7R-S2-MU  [C0201]  311.03 249.2 180 top
UNK2GND1  TP01  [TP_040_T]  450.43 295.27 0 top
UNK2GND2  TP01  [TP_040_T]  463.97 295.27 180 top
UNK2GND3  TP01  [TP_040_T]  483.45 295.27 0 top
UNK2GND4  TP01  [TP_040_T]  450.43 278.76 0 top
UNK2GND5  TP01  [TP_040_T]  463.97 278.76 180 top
UNK2GND6  TP01  [TP_040_T]  483.45 278.76 0 top
UNK2GND7  TP01  [TP_040_T]  480.48 295.27 180 top
UNK2GND8  TP01  [TP_040_T]  466.94 295.27 0 top
UNK2GND9  TP01  [TP_040_T]  480.48 278.76 180 top
UNK2GND10  TP01  [TP_040_T]  90.11 249.76 0 top
UNK2GND11  TP01  [TP_040_T]  85.24 249.81 0 top
UNK2GND12  TP01  [TP_040_T]  513.5 295.27 180 top
UNK2GND13  TP01  [TP_040_T]  496.99 278.76 180 top
UNK2GND14  TP01  [TP_040_T]  466.94 278.76 0 top
UNK2J1  HDR-2X1-M  [JP_2P_100]  468.63 233.43 90 bottom
UNK2J2  HDR-3X1-M  [JP_3P_100]  490.87 228.66 270 bottom
UNK2J3  HDR-3X1-M  [JP_3P_100]  490.87 214.94 270 bottom
UNK2J4  HDR-2X1-M  [JP_2P_100]  483.11 243.33 270 bottom
UNK2J5  HDR-2X1-M  [JP_2P_100]  483.11 231.65 270 bottom
UNK2K1  G6K-2F-RF-T-5V-SPECIAL  [RL_G6K2FRT_8P_5V_GR]  414.27 293.12 0 bottom
UNK2K2  G6K-2F-RF-T-5V-SPECIAL  [RL_G6K2FRT_8P_5V_GR]  373.13 245.11 0 bottom
UNK2K3  G6K-2F-RF-T-5V-SPECIAL  [RL_G6K2FRT_8P_5V_GR]  400.3 261.37 0 bottom
UNK2K4  G6K-2F-RF-T-5V-SPECIAL  [RL_G6K2FRT_8P_5V_GR]  373.13 261.11 0 bottom
UNK2K5  G6K-2F-RF-T-5V-SPECIAL  [RL_G6K2FRT_8P_5V_GR]  414.02 261.37 0 bottom
UNK2K6  G6K-2F-RF-T-5V-SPECIAL  [RL_G6K2FRT_8P_5V_GR]  414.27 277.37 0 bottom
UNK2K7  G6K-2F-RF-T-5V-SPECIAL  [RL_G6K2FRT_8P_5V_GR]  400.3 277.11 0 bottom
UNK2K8  G6K-2F-RF-T-5V-SPECIAL  [RL_G6K2FRT_8P_5V_GR]  386.84 293.12 0 bottom
UNK2K9  UA2-5NJ-A-V3  [RL_NECUA2_5V_V3]  299.96 235.46 90 bottom
UNK2K10  UA2-5NJ-A-V3  [RL_NECUA2_5V_V3]  467.11 228.6 180 bottom
UNK2K11  G6K-2F-RF-T-5V-SPECIAL  [RL_G6K2FRT_8P_5V_GR]  386.84 277.11 0 bottom
UNK2K12  UA2-5NJ-A-V3  [RL_NECUA2_5V_V3]  299.96 246.89 90 bottom
UNK2K13  UA2-5NJ-A-V3  [RL_NECUA2_5V_V3]  455.68 228.6 0 bottom
UNK2K14  UA2-5NJ-A-V3  [RL_NECUA2_5V_V3]  467.61 213.36 0 bottom
UNK2K15  UA2-5NJ-A-V3  [RL_NECUA2_5V_V3]  455.64 220.9 0 bottom
UNK2K16  G6K-2F-RF-T-5V-SPECIAL  [RL_G6K2FRT_8P_5V_GR]  373.38 277.11 0 bottom
UNK2K17  G6K-2F-RF-T-5V-SPECIAL  [RL_G6K2FRT_8P_5V_GR]  400.3 293.12 0 bottom
UNK2K18  UB2-5NU-B  [RL_NECUB2_5V]  308.45 274.32 0 bottom
UNK2K19  UA2-5NJ-A-V3  [RL_NECUA2_5V_V3]  467.61 220.98 0 bottom
UNK2K20  UA2-5NJ-A-V3  [RL_NECUA2_5V_V3]  455.68 213.36 0 bottom
UNK2K21  G6K-2F-RF-T-5V-SPECIAL  [RL_G6K2FRT_8P_5V_GR]  373.38 293.12 0 bottom
UNK2K22  G6K-2F-RF-T-5V-SPECIAL  [RL_G6K2FRT_8P_5V_GR]  400.3 229.11 0 bottom
UNK2K23  G6K-2F-RF-T-5V-SPECIAL  [RL_G6K2FRT_8P_5V_GR]  407.16 213.61 0 bottom
UNK2K24  G6K-2F-RF-T-5V-SPECIAL  [RL_G6K2FRT_8P_5V_GR]  393.45 213.36 0 bottom
UNK2K25  G6K-2F-RF-T-5V-SPECIAL  [RL_G6K2FRT_8P_5V_GR]  414.27 245.11 0 bottom
UNK2K26  G6K-2F-RF-T-5V-SPECIAL  [RL_G6K2FRT_8P_5V_GR]  373.13 228.6 0 bottom
UNK2K27  G6K-2F-RF-T-5V-SPECIAL  [RL_G6K2FRT_8P_5V_GR]  386.84 228.85 0 bottom
UNK2K28  UA2-5NJ-A-V3  [RL_NECUA2_5V_V3]  479.04 237.49 180 bottom
UNK2K29  G6K-2F-RF-T-5V-SPECIAL  [RL_G6K2FRT_8P_5V_GR]  386.84 245.11 0 bottom
UNK2K30  G6K-2F-RF-T-5V-SPECIAL  [RL_G6K2FRT_8P_5V_GR]  400.3 245.11 0 bottom
UNK2K31  EC2-5NJ-A  [RL_NECEC2_10P_5V]  506.73 294.64 90 bottom
UNK2K33  NC/UA2-5NJ-A-V3  [RL_NECUA2_5V_V3]  455.68 237.74 0 bottom
UNK2K34  EC2-5NJ-A  [RL_NECEC2_10P_5V]  457.2 294.64 90 bottom
UNK2K36  EC2-5NJ-A  [RL_NECEC2_10P_5V]  490.22 294.64 90 bottom
UNK2K37  EC2-5NJ-A  [RL_NECEC2_10P_5V]  457.2 278.13 90 bottom
UNK2K39  EC2-5NJ-A  [RL_NECEC2_10P_5V]  490.22 278.13 90 bottom
UNK2K40  EC2-5NJ-A  [RL_NECEC2_10P_5V]  473.71 294.64 90 bottom
UNK2K42  EC2-5NJ-A  [RL_NECEC2_10P_5V]  473.71 278.13 90 bottom
UNK2K43  G6K-2F-RF-T-5V-SPECIAL  [RL_G6K2FRT_8P_5V_GR]  386.84 261.11 0 bottom
UNK2R1  NC/1M-1-S4  [R0402]  301.23 227.84 180 bottom
UNK2R2  NC/1M-1-S4  [R0402]  298.95 227.84 0 bottom
UNK2R3  NC/100K-1-S4  [R0402]  289.81 130.81 180 bottom
UNK2R4  NC/100K-1-S4  [R0402]  287.27 130.81 180 bottom
UNK2R5  0-5-S4  [R0402]  302.38 272.16 270 bottom
UNK2R6  1M-1-S4  [R0402]  302.38 274.32 270 bottom
UNK2R7  49.9-1-S4  [R0402]  415.95 299.91 180 bottom
UNK2R8  49.9-1-S4  [R0402]  418.1 299.91 180 bottom
UNK2R9  49.9-1-S4  [R0402]  415.95 286.32 180 bottom
UNK2R10  49.9-1-S4  [R0402]  418.1 286.32 180 bottom
UNK2R11  49.9-1-S4  [R0402]  374.8 251.9 180 bottom
UNK2R12  49.9-1-S4  [R0402]  376.95 251.9 180 bottom
UNK2R13  49.9-1-S4  [R0402]  374.8 238.32 180 bottom
UNK2R14  49.9-1-S4  [R0402]  376.95 238.32 180 bottom
UNK2R15  49.9-1-S4  [R0402]  401.98 268.16 180 bottom
UNK2R16  49.9-1-S4  [R0402]  404.13 268.16 180 bottom
UNK2R17  49.9-1-S4  [R0402]  401.98 254.57 180 bottom
UNK2R18  49.9-1-S4  [R0402]  404.13 254.57 180 bottom
UNK2R19  49.9-1-S4  [R0402]  374.8 267.91 180 bottom
UNK2R20  49.9-1-S4  [R0402]  376.95 267.91 180 bottom
UNK2R21  49.9-1-S4  [R0402]  374.8 254.32 180 bottom
UNK2R22  49.9-1-S4  [R0402]  376.95 254.32 180 bottom
UNK2R23  49.9-1-S4  [R0402]  415.7 268.16 180 bottom
UNK2R24  49.9-1-S4  [R0402]  417.84 268.16 180 bottom
UNK2R25  49.9-1-S4  [R0402]  415.7 254.57 180 bottom
UNK2R26  49.9-1-S4  [R0402]  417.84 254.57 180 bottom
UNK2R27  49.9-1-S4  [R0402]  415.95 284.16 180 bottom
UNK2R28  49.9-1-S4  [R0402]  418.1 284.16 180 bottom
UNK2R29  49.9-1-S4  [R0402]  415.95 270.57 180 bottom
UNK2R30  49.9-1-S4  [R0402]  418.1 270.57 180 bottom
UNK2R31  49.9-1-S4  [R0402]  401.98 283.91 180 bottom
UNK2R32  49.9-1-S4  [R0402]  404.13 283.91 180 bottom
UNK2R33  49.9-1-S4  [R0402]  401.98 270.32 180 bottom
UNK2R34  49.9-1-S4  [R0402]  404.13 270.32 180 bottom
UNK2R37  49.9-1-S4  [R0402]  388.52 286.32 180 bottom
UNK2R38  49.9-1-S4  [R0402]  390.66 286.32 180 bottom
UNK2R39  49.9-1-S4  [R0402]  388.52 283.91 180 bottom
UNK2R40  49.9-1-S4  [R0402]  390.66 283.91 180 bottom
UNK2R41  49.9-1-S4  [R0402]  388.52 270.32 180 bottom
UNK2R42  49.9-1-S4  [R0402]  390.66 270.32 180 bottom
UNK2R43  49.9-1-S4  [R0402]  388.52 238.32 180 bottom
UNK2R44  49.9-1-S4  [R0402]  390.66 238.32 180 bottom
UNK2R45  49.9-1-S4  [R0402]  401.98 222.31 180 bottom
UNK2R46  49.9-1-S4  [R0402]  404.13 222.31 180 bottom
UNK2R47  49.9-1-S4  [R0402]  408.84 220.41 180 bottom
UNK2R48  49.9-1-S4  [R0402]  410.98 220.41 180 bottom
UNK2R49  49.9-1-S4  [R0402]  408.84 206.82 180 bottom
UNK2R50  49.9-1-S4  [R0402]  410.98 206.82 180 bottom
UNK2R51  49.9-1-S4  [R0402]  395.12 220.15 180 bottom
UNK2R52  49.9-1-S4  [R0402]  397.27 220.15 180 bottom
UNK2R53  49.9-1-S4  [R0402]  395.12 206.57 180 bottom
UNK2R54  49.9-1-S4  [R0402]  397.27 206.57 180 bottom
UNK2R55  49.9-1-S4  [R0402]  415.95 251.9 180 bottom
UNK2R56  49.9-1-S4  [R0402]  418.1 251.9 180 bottom
UNK2R57  49.9-1-S4  [R0402]  415.95 238.32 180 bottom
UNK2R58  49.9-1-S4  [R0402]  418.1 238.32 180 bottom
UNK2R59  49.9-1-S4  [R0402]  374.8 235.39 180 bottom
UNK2R60  49.9-1-S4  [R0402]  376.95 235.39 180 bottom
UNK2R61  49.9-1-S4  [R0402]  374.8 221.81 180 bottom
UNK2R62  49.9-1-S4  [R0402]  376.95 221.81 180 bottom
UNK2R63  49.9-1-S4  [R0402]  401.98 251.9 180 bottom
UNK2R64  49.9-1-S4  [R0402]  404.13 251.9 180 bottom
UNK2R65  49.9-1-S4  [R0402]  388.52 222.06 180 bottom
UNK2R66  49.9-1-S4  [R0402]  390.66 222.06 180 bottom
UNK2R67  49.9-1-S4  [R0402]  375.06 283.91 180 bottom
UNK2R68  49.9-1-S4  [R0402]  377.2 283.91 180 bottom
UNK2R69  49.9-1-S4  [R0402]  375.06 270.32 180 bottom
UNK2R70  49.9-1-S4  [R0402]  377.2 270.32 180 bottom
UNK2R71  49.9-1-S4  [R0402]  401.98 299.91 180 bottom
UNK2R72  49.9-1-S4  [R0402]  404.13 299.91 180 bottom
UNK2R73  49.9-1-S4  [R0402]  401.98 286.32 180 bottom
UNK2R74  49.9-1-S4  [R0402]  404.13 286.32 180 bottom
UNK2R75  49.9-1-S4  [R0402]  375.06 299.91 180 bottom
UNK2R76  49.9-1-S4  [R0402]  377.2 299.91 180 bottom
UNK2R77  49.9-1-S4  [R0402]  375.06 286.32 180 bottom
UNK2R78  49.9-1-S4  [R0402]  377.2 286.32 180 bottom
UNK2R79  49.9-1-S4  [R0402]  388.52 251.9 180 bottom
UNK2R80  49.9-1-S4  [R0402]  390.66 251.9 180 bottom
UNK2R82  4.7K-1-S4-WA  [R0402]  456.75 233.88 0 bottom
UNK2R83  4.7K-1-S4-WA  [R0402]  482.6 241.3 0 bottom
UNK2R84  4.7K-1-S4-WA  [R0402]  482.6 233.68 0 bottom
UNK2R85  100K-1-S4  [R0402]  465.07 235.71 0 bottom
UNK2R86  4.7K-1-S4-WA  [R0402]  486.3 226.62 0 bottom
UNK2R87  4.7K-1-S4-WA  [R0402]  475.49 230.78 0 bottom
UNK2R88  4.7K-1-S4-WA  [R0402]  478.03 230.78 0 bottom
UNK2R89  4.7K-1-S4-WA  [R0402]  490.6 226.67 180 bottom
UNK2R90  4.7K-1-S4-WA  [R0402]  478.03 218.59 0 bottom
UNK2R91  4.7K-1-S4-WA  [R0402]  480.57 218.59 0 bottom
UNK2R92  4.7K-1-S4-WA  [R0402]  483.11 218.59 0 bottom
UNK2R93  4.7K-1-S4-WA  [R0402]  486.3 212.91 0 bottom
UNK2R94  4.7K-1-S4-WA  [R0402]  475.37 217.23 180 bottom
UNK2R95  4.7K-1-S4-WA  [R0402]  477.93 217.17 0 bottom
UNK2R96  4.7K-1-S4-WA  [R0402]  490.36 212.91 180 bottom
UNK2R97  4.7K-1-S4-WA  [R0402]  477.93 204.98 0 bottom
UNK2R98  4.7K-1-S4-WA  [R0402]  480.47 204.98 0 bottom
UNK2R99  4.7K-1-S4-WA  [R0402]  483.01 204.98 0 bottom
UNK2R100  49.9-1-S4  [R0402]  401.98 238.32 180 bottom
UNK2R101  49.9-1-S4  [R0402]  404.13 238.32 180 bottom
UNK2R102  49.9-1-S4  [R0402]  401.98 235.9 180 bottom
UNK2R103  49.9-1-S4  [R0402]  404.13 235.9 180 bottom
UNK2R104  49.9-1-S4  [R0402]  388.52 235.65 180 bottom
UNK2R105  49.9-1-S4  [R0402]  390.66 235.65 180 bottom
UNK2R117  1K-1-S4  [R0402]  452.18 233.88 0 bottom
UNK2R118  NC/0-5-S4  [R0402]  310.41 245.39 180 bottom
UNK2R119  4.7K-1-S4-WA  [R0402]  452.12 224.79 180 bottom
UNK2R120  4.7K-1-S4-WA  [R0402]  452.12 232.41 180 bottom
UNK2R125  0-5-S4  [R0402]  456.44 209.55 0 bottom
UNK2R126  0-5-S4  [R0402]  452.37 209.55 0 bottom
UNK2R127  0-5-S4  [R0402]  456.69 217.17 0 bottom
UNK2R128  0-5-S4  [R0402]  452.12 217.17 0 bottom
UNK2R129  0-5-S4  [R0402]  301.23 229.11 180 bottom
UNK2R130  0-5-S4  [R0402]  298.95 229.11 0 bottom
UNK2R131  50-0.1-S4-HF-VI  [R0402]  303.77 243.33 90 bottom
UNK2R132  50-0.1-S4-HF-VI  [R0402]  296.15 243.33 90 bottom
UNK2R133  0-5-S4  [R0402]  302.38 276.48 90 bottom
UNK2SH1  SHORT  [DEFAULT_SHORT_SMALL]  462.05 291.99 0 top
UNK2SH2  SHORT  [DEFAULT_SHORT_SMALL]  464 291.99 0 top
UNK2SH3  SHORT  [DEFAULT_SHORT_SMALL]  452.21 291.99 0 top
UNK2SH4  SHORT  [DEFAULT_SHORT_SMALL]  450.26 292.12 180 top
UNK2SH5  SHORT  [DEFAULT_SHORT_SMALL]  485.23 291.99 0 top
UNK2SH6  SHORT  [DEFAULT_SHORT_SMALL]  483.28 292.12 180 top
UNK2SH7  SHORT  [DEFAULT_SHORT_SMALL]  462.05 275.48 0 top
UNK2SH8  SHORT  [DEFAULT_SHORT_SMALL]  450.26 275.61 180 top
UNK2SH9  SHORT  [DEFAULT_SHORT_SMALL]  464 275.48 0 top
UNK2SH10  SHORT  [DEFAULT_SHORT_SMALL]  452.21 275.48 0 top
UNK2SH11  SHORT  [DEFAULT_SHORT_SMALL]  483.28 275.61 180 top
UNK2SH12  SHORT  [DEFAULT_SHORT_SMALL]  495.07 275.48 0 top
UNK2SH13  SHORT  [DEFAULT_SHORT_SMALL]  480.51 291.99 0 top
UNK2SH14  SHORT  [DEFAULT_SHORT_SMALL]  478.56 291.99 0 top
UNK2SH15  SHORT  [DEFAULT_SHORT_SMALL]  466.77 292.12 180 top
UNK2SH16  SHORT  [DEFAULT_SHORT_SMALL]  468.72 291.99 0 top
UNK2SH17  SHORT  [DEFAULT_SHORT_SMALL]  466.77 275.61 180 top
UNK2SH18  SHORT  [DEFAULT_SHORT_SMALL]  478.56 275.48 0 top
UNK2SH19  SHORT  [DEFAULT_SHORT_SMALL]  90.17 246.75 0 top
UNK2SH20  SHORT  [DEFAULT_SHORT_SMALL]  92.37 246.75 0 top
UNK2SH21  SHORT  [DEFAULT_SHORT_SMALL]  85.31 246.8 0 top
UNK2SH22  SHORT  [DEFAULT_SHORT_SMALL]  87.51 246.8 0 top
UNK2SH23  SHORT  [DEFAULT_SHORT_SMALL]  511.58 291.99 0 top
UNK2SH24  SHORT  [DEFAULT_SHORT_SMALL]  513.76 291.86 180 top
UNK2SH25  SHORT  [DEFAULT_SHORT_SMALL]  485.23 275.48 0 top
UNK2SH26  SHORT  [DEFAULT_SHORT_SMALL]  497.02 275.48 0 top
UNK2SH27  SHORT  [DEFAULT_SHORT_SMALL]  468.72 275.48 0 top
UNK2SH28  SHORT  [DEFAULT_SHORT_SMALL]  480.51 275.48 0 top
UNK2TP_AUXVCC  TP01  [TP_040_T]  92.04 247.9 180 top
UNK2TP_AVDD11_RX  TP01  [TP_040_T]  452.33 276.86 180 top
UNK2TP_AVDD11_XTAL  TP01  [TP_040_T]  511.6 293.37 0 top
UNK2TP_AVDD18_RX  TP01  [TP_040_T]  462.07 276.86 0 top
UNK2TP_PLL_M_VDD33  TP01  [TP_040_T]  478.58 293.37 0 top
UNK2TP_PLL_TX_VDD33  TP01  [TP_040_T]  468.84 293.37 180 top
UNK2TP_VCC3V3  TP01  [TP_040_T]  87.17 247.96 180 top
UNK2TP_VDD_IO_33  TP01  [TP_040_T]  452.33 293.37 180 top
UNK2TP_VDD_TXREG_33_B  TP01  [TP_040_T]  478.58 276.86 0 top
UNK2TP_VDD_TXREG_33_T  TP01  [TP_040_T]  468.84 276.86 180 top
UNK2TP_VDDA_33_LV  TP01  [TP_040_T]  462.07 293.37 0 top
UNK2TP_VDDC_11  TP01  [TP_040_T]  485.35 293.37 180 top
UNK2TP_VDDTXPST_11_B  TP01  [TP_040_T]  495.09 276.86 0 top
UNK2TP_VDDTXPST_11_T  TP01  [TP_040_T]  485.35 276.86 180 top
UNK2TP_XTAL_IN  TP01  [TP_040_T]  306.85 271.67 0 top
UNK2TP_XTAL_OUT  TP01  [TP_040_T]  306.85 276.97 0 top
UNK2U1  SOLDER-DIP8-SOCKET  [DIP8_300X100_RLPIN]  474.97 228.55 270 bottom
UNK2U2  SOLDER-DIP8-SOCKET  [DIP8_300X100_RLPIN]  474.87 214.94 270 bottom
UNK2UF1  MX25L4006EM2I-12G-SOP8  [SOCKET_CODE]  360.09 283.74 180 top
UNK2UF2  MX25L4006EM2I-12G-SOP8  [SOCKET_CODE]  474.97 228.55 90 top
UNK2Y1  XTAL27M-S2520-ABRACON-10P  [XTAL_2X2P5MM_4P]  298.76 274.89 270 bottom
UNK2Y2  NC/XTAL27M-S3225-TXC-10P  [XTAL_3P2X2P5MM_4P_TXC_0201]  298.76 274.89 270 bottom
UNK3C3  0.1U-16-X-S4-MU  [C0402]  192.28 132.33 180 bottom
UNK3C4  0.1U-16-X-S4-MU  [C0402]  189.74 132.33 180 bottom
UNK3C5  22P-50-N-S4-AVX  [C0402]  221.21 217.48 90 bottom
UNK3C6  22P-50-N-S4-AVX  [C0402]  221.21 211.16 270 bottom
UNK3C7  0.1U-16-X-S4-MU  [C0402]  111 186.44 0 bottom
UNK3C8  0.1U-16-X-S4-MU  [C0402]  104.39 171.81 180 bottom
UNK3C9  0.1U-16-X-S4-MU  [C0402]  104.49 185.42 180 bottom
UNK3CA1  NC/10U-10-X6S-S6-MU  [C0603]  112.39 290.83 0 bottom
UNK3CA2  NC/47U-10-X5R-S8-TDK  [C0805]  112.5 292.74 0 bottom
UNK3CA3  NC/10U-10-X6S-S6-MU  [C0603]  100.96 290.83 180 bottom
UNK3CA4  NC/47U-10-X5R-S8-TDK  [C0805]  100.86 292.74 180 bottom
UNK3CA5  NC/10U-10-X6S-S6-MU  [C0603]  100.96 274.32 180 bottom
UNK3CA6  NC/47U-10-X5R-S8-TDK  [C0805]  100.86 276.23 180 bottom
UNK3CA7  NC/10U-10-X6S-S6-MU  [C0603]  128.9 274.32 0 bottom
UNK3CA8  NC/47U-10-X5R-S8-TDK  [C0805]  129.01 276.23 0 bottom
UNK3CA9  NC/10U-10-X6S-S6-MU  [C0603]  117.47 274.32 180 bottom
UNK3CA10  NC/47U-10-X5R-S8-TDK  [C0805]  117.37 276.23 180 bottom
UNK3CA11  NC/10U-10-X6S-S6-MU  [C0603]  76.83 290.83 0 bottom
UNK3CA12  NC/47U-10-X5R-S8-TDK  [C0805]  76.94 292.74 0 bottom
UNK3CA13  NC/47U-10-X5R-S8-TDK  [C0805]  94.72 292.74 0 bottom
UNK3CA14  NC/10U-10-X6S-S6-MU  [C0603]  94.61 290.83 0 bottom
UNK3CA15  NC/47U-10-X5R-S8-TDK  [C0805]  83.08 292.74 180 bottom
UNK3CA16  NC/10U-10-X6S-S6-MU  [C0603]  83.18 290.83 180 bottom
UNK3CA17  NC/47U-10-X5R-S8-TDK  [C0805]  76.94 276.23 0 bottom
UNK3CA18  NC/10U-10-X6S-S6-MU  [C0603]  76.83 274.32 0 bottom
UNK3CA19  NC/47U-10-X5R-S8-TDK  [C0805]  111.1 249.13 180 bottom
UNK3CA20  NC/10U-10-X6S-S6-MU  [C0603]  111.2 247.23 180 bottom
UNK3CA21  10U-10-X6S-S6-MU  [C0603]  112.39 288.29 0 bottom
